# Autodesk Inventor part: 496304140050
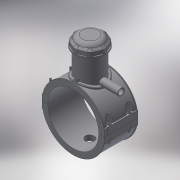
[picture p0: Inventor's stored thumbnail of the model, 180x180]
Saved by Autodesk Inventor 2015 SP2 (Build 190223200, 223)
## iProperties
Created: 2017-07
Part Number: 496304140050
Material: Generic
Description: PLASSON TAPPING SADDLE 140x50
Document SubType Name: Modeling
Designer: KIM
Mass: 956.685 g
Surface Area: 2287.91 cm^2
Volume: 956.685 cm^3
Density: 1 g/cm^3
Appearance: Default
Author: KIM
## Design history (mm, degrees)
derived "496304.ipt"
feature "Solid1::496304.ipt"
feature "Solid2::496304.ipt"
feature "Solid4::496304.ipt"
feature "Solid5::496304.ipt"
tag "TaggingFeature1"
body "Solid1"
body "Solid2"
other parameters: "d3" = 35, "d4" = 118, "d5" = 0, "d6" = 0.1, "d8" = 0, "d19" = 6, "d20" = 6, "d21" = 70.8, "d23" = 0, "d24" = 35.4, "d26" = 0, "d29" = 3, "d30" = 46.66667, "d31" = 6, "d32" = 0, "d33" = 0, "d34" = 0.6, "d40" = 82.992, "d43" = 0, "d45" = 0, "d47" = 150.6, "d70" = 15, "d72" = 0, "d73" = 6, "d75" = 5, "d76" = 0, "d77" = 7, "d79" = 15, "d80" = 47.2, "d82" = 5 deg, "d84" = 4, "d85" = 14, "d86" = 0, "d87" = 3, "d88" = 0, "d89" = 1, "d90" = 1, "d91" = 94.4, "d92" = 0, "d93" = 0.5, "d94" = 73.68421, "d96" = 162.792, "d97" = 2.36, "d98" = 0, "d102" = 1.4, "d120" = 140 deg, "d121" = 24.228, "d122" = 20 deg, "d123" = 319.2, "d124" = 95.76, "d126" = 0, "d143" = 144.2, "d145" = 15.07692, "d149" = 2.1, "d150" = 16.58462, "d153" = 118, "d154" = 0, "d156" = 79.8, "d157" = 160 deg, "d159" = 3.92, "d161" = 2.1, "d162" = 70.8, "d163" = 0, "d167" = 14, "d168" = 77.85366, "d170" = 3.375, "d172" = 0, "d173" = 1, "d176" = 20 deg, "d177" = 9.8, "d178" = 19.6, "d180" = 0, "d183" = 7.84, "d184" = 7.84, "d185" = 38.35, "d186" = 38.35, "d187" = 79.8, "d188" = 5.88, "d189" = 9.8, "d190" = 0, "d191" = 119.7, "d193" = 6.3, "d194" = 4.13, "d195" = 90 deg, "d197" = 0, "d199" = 0, "d200" = 9.8, "d202" = 0, "d203" = 177, "d204" = 66.5, "d205" = 49, "d206" = 59.5, "d207" = 132.75, "d208" = 138.06, "d209" = 164.61, "d210" = 60.2, "d212" = 56, "d213" = 35.1, "d216" = 0, "d217" = 14, "d218" = 14, "d219" = 2.8, "d224" = 0, "d230" = 5.6, "d233" = 6, "d237" = 35.4, "d238" = 6.02433, "d240" = 35.4, "d241" = 35.4, "d242" = 35.4, "d243" = 6, "d244" = 35.4, "d245" = 35.4, "d246" = 35.4, "d247" = 6, "d248" = 6, "d249" = 6, "d251" = 35.4, "d253" = 6, "d254" = 6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
